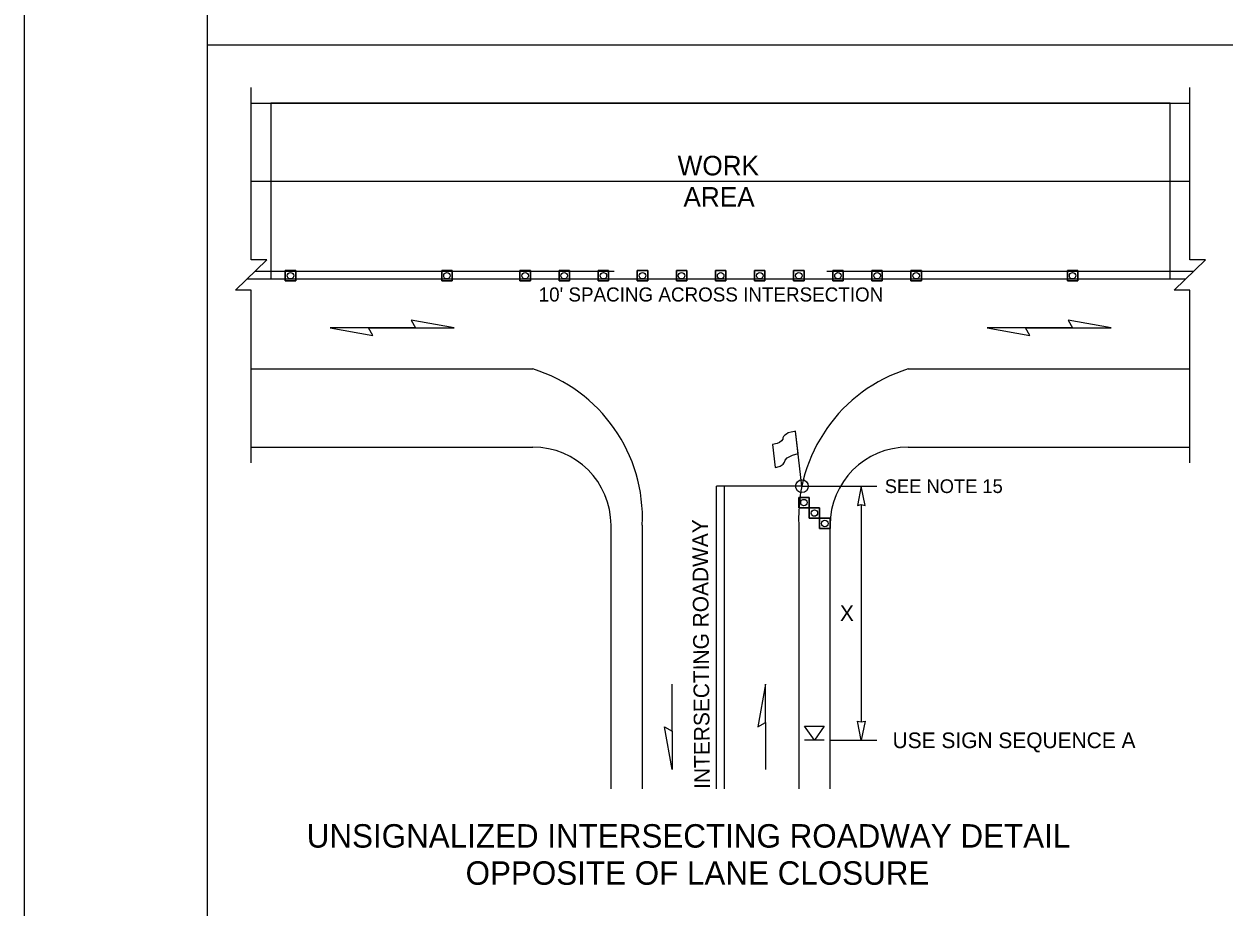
# Model space of a CAD drawing. Extents: x 99999.1 to 100095.7, y 99995 to 100010.7.
# Drawn here: x 100059.06 to 100065.2, y 100001.57 to 100006.09 of the extents above; entities that cross this region are included whole.
import ezdxf

# ---------------------------------------------------------------- set-up
doc = ezdxf.new("R2010")
doc.units = 0
for name, color, linetype in [('RD_ED_ShoulderPavedEdge', 7, 'Continuous'), ('RD_MK_LineDblYellowCenter', 7, 'Continuous'), ('RD_MK_LineEdgeWhite', 7, 'Continuous'), ('RD_MK_LineStop', 7, 'Continuous'), ('SH_DE_DetailBody1Text', 7, 'Continuous'), ('SH_DE_DetailHeading2Text', 7, 'Continuous'), ('SH_GI_PlotLimits', 7, 'Continuous'), ('SH_GI_SheetBorder', 7, 'Continuous'), ('TR_WZ_FlaggingStation', 7, 'Continuous'), ('TR_WZ_PortableSignMountBlk-Org', 7, 'Continuous'), ('TR_WZ_TrafficCone', 7, 'Continuous'), ('TR_WZ_WorkAreaLabel', 7, 'Continuous'), ('TR_WZ_WorkZoneDetails', 7, 'Continuous'), ('TR_WZ_WorkZoneTextCurrent', 7, 'Continuous')]:
    doc.layers.add(name, color=color, linetype=linetype)

msp = doc.modelspace()

# ---------------------------------------------------------------- linework, layer by layer
at = {"layer": 'RD_ED_ShoulderPavedEdge'}
for p, q in [((100060.225, 100005.6849), (100065.025, 100005.6849)), ((100060.225, 100003.9249), (100061.665, 100003.9249)), ((100063.585, 100003.9249), (100065.025, 100003.9249))]:
    msp.add_line(p, q, dxfattribs=at)
for points in [[(100062.065, 100002.1759), (100062.065, 100003.5249)], [(100063.185, 100002.1759), (100063.185, 100003.5249)]]:
    msp.add_lwpolyline(points, dxfattribs=at)
for centre, start, end in [((100061.665, 100003.5249), 0, 90), ((100063.585, 100003.5249), 90, 180)]:
    msp.add_arc(centre, 0.4, start, end, dxfattribs=at)
at = {"layer": 'RD_MK_LineDblYellowCenter'}
for p, q in [((100060.2457, 100004.8249), (100062.0812, 100004.8249)), ((100063.1688, 100004.8249), (100065.0457, 100004.8249)), ((100060.2043, 100004.7849), (100062.0812, 100004.7849)), ((100063.1688, 100004.7849), (100065.0043, 100004.7849)), ((100062.605, 100002.1759), (100062.605, 100003.7249)), ((100062.645, 100002.1759), (100062.645, 100003.7249))]:
    msp.add_line(p, q, dxfattribs=at)
at = {"layer": 'RD_MK_LineEdgeWhite'}
for p, q in [((100060.225, 100005.2849), (100065.025, 100005.2849)), ((100060.225, 100004.3249), (100061.665, 100004.3249)), ((100063.585, 100004.3249), (100065.025, 100004.3249)), ((100062.225, 100003.5249), (100062.225, 100002.1759)), ((100063.025, 100003.5249), (100063.025, 100002.1759))]:
    msp.add_line(p, q, dxfattribs=at)
for centre, start, end in [((100061.4258, 100003.5615), 357.37881, 72.60523), ((100063.8242, 100003.5615), 107.39477, 182.62119)]:
    msp.add_arc(centre, 0.8, start, end, dxfattribs=at)
at = {"layer": 'RD_MK_LineStop'}
msp.add_line((100063.041, 100003.7249), (100062.605, 100003.7249), dxfattribs=at)
at = {"layer": 'SH_GI_PlotLimits'}
msp.add_lwpolyline([(100059.0625, 99999.6875), (100076.0625, 99999.6875), (100076.0625, 100010.6875), (100059.0625, 100010.6875)], close=True, dxfattribs=at)
at = {"layer": 'SH_GI_SheetBorder'}
msp.add_line((100060, 100010.375), (100060, 100000), dxfattribs=at)
at = {"layer": 'TR_WZ_FlaggingStation'}
for p, q in [((100063.022, 100003.8918), (100063.0089, 100004.0062)), ((100063.041, 100003.7249), (100063.009, 100004.0059)), ((100062.891, 100003.9384), (100062.9043, 100003.8212)), ((100063.022, 100003.8918), (100063.022, 100003.8918))]:
    msp.add_line(p, q, dxfattribs=at)
for points in [[(100063.0089, 100004.0062), (100063.0032, 100004.0049), (100062.9854, 100004.0015), (100062.9715, 100003.9973), (100062.9619, 100003.9912), (100062.9533, 100003.9865), (100062.9477, 100003.9797), (100062.9434, 100003.9718), (100062.9429, 100003.9656), (100062.9375, 100003.9564), (100062.9267, 100003.949), (100062.9143, 100003.9438), (100062.891, 100003.9384)], [(100062.9043, 100003.8212), (100062.9124, 100003.8226), (100062.9301, 100003.8272), (100062.9458, 100003.8377), (100062.9523, 100003.8483), (100062.9562, 100003.8586), (100062.9653, 100003.8695), (100062.9763, 100003.8757), (100062.9936, 100003.8828), (100063.022, 100003.8918)]]:
    msp.add_lwpolyline(points, dxfattribs=at)
msp.add_circle((100063.041, 100003.7249), 0.0325, dxfattribs=at)
at = {"layer": 'TR_WZ_PortableSignMountBlk-Org'}
msp.add_line((100063.1549, 100002.4249), (100063.0549, 100002.4249), dxfattribs=at)
msp.add_lwpolyline([(100063.105, 100002.4249), (100063.0549, 100002.4968), (100063.1549, 100002.4968)], close=True, dxfattribs=at)
at = {"layer": 'TR_WZ_TrafficCone'}
for points in [[(100060.399, 100004.8283), (100060.4524, 100004.8283), (100060.4524, 100004.7749), (100060.399, 100004.7749), (100060.399, 100004.8283)], [(100060.399, 100004.7749), (100060.4524, 100004.7749), (100060.4524, 100004.8283), (100060.399, 100004.8283), (100060.399, 100004.7749)], [(100061.199, 100004.8283), (100061.2524, 100004.8283), (100061.2524, 100004.7749), (100061.199, 100004.7749), (100061.199, 100004.8283)], [(100061.199, 100004.7749), (100061.2524, 100004.7749), (100061.2524, 100004.8283), (100061.199, 100004.8283), (100061.199, 100004.7749)], [(100061.599, 100004.8283), (100061.6524, 100004.8283), (100061.6524, 100004.7749), (100061.599, 100004.7749), (100061.599, 100004.8283)], [(100061.599, 100004.7749), (100061.6524, 100004.7749), (100061.6524, 100004.8283), (100061.599, 100004.8283), (100061.599, 100004.7749)], [(100061.799, 100004.8283), (100061.8524, 100004.8283), (100061.8524, 100004.7749), (100061.799, 100004.7749), (100061.799, 100004.8283)], [(100061.799, 100004.7749), (100061.8524, 100004.7749), (100061.8524, 100004.8283), (100061.799, 100004.8283), (100061.799, 100004.7749)], [(100061.999, 100004.8283), (100062.0524, 100004.8283), (100062.0524, 100004.7749), (100061.999, 100004.7749), (100061.999, 100004.8283)], [(100061.999, 100004.7749), (100062.0524, 100004.7749), (100062.0524, 100004.8283), (100061.999, 100004.8283), (100061.999, 100004.7749)], [(100062.199, 100004.8283), (100062.2524, 100004.8283), (100062.2524, 100004.7749), (100062.199, 100004.7749), (100062.199, 100004.8283)], [(100062.199, 100004.7749), (100062.2524, 100004.7749), (100062.2524, 100004.8283), (100062.199, 100004.8283), (100062.199, 100004.7749)], [(100062.399, 100004.8283), (100062.4524, 100004.8283), (100062.4524, 100004.7749), (100062.399, 100004.7749), (100062.399, 100004.8283)], [(100062.399, 100004.7749), (100062.4524, 100004.7749), (100062.4524, 100004.8283), (100062.399, 100004.8283), (100062.399, 100004.7749)], [(100062.599, 100004.8283), (100062.6524, 100004.8283), (100062.6524, 100004.7749), (100062.599, 100004.7749), (100062.599, 100004.8283)], [(100062.599, 100004.7749), (100062.6524, 100004.7749), (100062.6524, 100004.8283), (100062.599, 100004.8283), (100062.599, 100004.7749)], [(100062.799, 100004.8283), (100062.8524, 100004.8283), (100062.8524, 100004.7749), (100062.799, 100004.7749), (100062.799, 100004.8283)], [(100062.799, 100004.7749), (100062.8524, 100004.7749), (100062.8524, 100004.8283), (100062.799, 100004.8283), (100062.799, 100004.7749)], [(100062.999, 100004.8283), (100063.0524, 100004.8283), (100063.0524, 100004.7749), (100062.999, 100004.7749), (100062.999, 100004.8283)], [(100062.999, 100004.7749), (100063.0524, 100004.7749), (100063.0524, 100004.8283), (100062.999, 100004.8283), (100062.999, 100004.7749)], [(100063.199, 100004.8283), (100063.2524, 100004.8283), (100063.2524, 100004.7749), (100063.199, 100004.7749), (100063.199, 100004.8283)], [(100063.199, 100004.7749), (100063.2524, 100004.7749), (100063.2524, 100004.8283), (100063.199, 100004.8283), (100063.199, 100004.7749)], [(100063.399, 100004.8283), (100063.4524, 100004.8283), (100063.4524, 100004.7749), (100063.399, 100004.7749), (100063.399, 100004.8283)], [(100063.399, 100004.7749), (100063.4524, 100004.7749), (100063.4524, 100004.8283), (100063.399, 100004.8283), (100063.399, 100004.7749)], [(100063.599, 100004.8283), (100063.6524, 100004.8283), (100063.6524, 100004.7749), (100063.599, 100004.7749), (100063.599, 100004.8283)], [(100063.599, 100004.7749), (100063.6524, 100004.7749), (100063.6524, 100004.8283), (100063.599, 100004.8283), (100063.599, 100004.7749)], [(100064.399, 100004.8283), (100064.4524, 100004.8283), (100064.4524, 100004.7749), (100064.399, 100004.7749), (100064.399, 100004.8283)], [(100064.399, 100004.7749), (100064.4524, 100004.7749), (100064.4524, 100004.8283), (100064.399, 100004.8283), (100064.399, 100004.7749)], [(100063.025, 100003.6142), (100063.025, 100003.6676), (100063.0783, 100003.6676), (100063.0783, 100003.6142), (100063.025, 100003.6142)], [(100063.0783, 100003.6142), (100063.0783, 100003.6676), (100063.025, 100003.6676), (100063.025, 100003.6142), (100063.0783, 100003.6142)], [(100063.0783, 100003.5609), (100063.0783, 100003.6142), (100063.1317, 100003.6142), (100063.1317, 100003.5609), (100063.0783, 100003.5609)], [(100063.1317, 100003.5609), (100063.1317, 100003.6142), (100063.0783, 100003.6142), (100063.0783, 100003.5609), (100063.1317, 100003.5609)], [(100063.1317, 100003.5076), (100063.1317, 100003.5609), (100063.185, 100003.5609), (100063.185, 100003.5076), (100063.1317, 100003.5076)], [(100063.185, 100003.5076), (100063.185, 100003.5609), (100063.1317, 100003.5609), (100063.1317, 100003.5076), (100063.185, 100003.5076)]]:
    msp.add_lwpolyline(points, dxfattribs=at)
for centre in [(100060.4257, 100004.8016), (100061.2257, 100004.8016), (100061.6257, 100004.8016), (100061.8257, 100004.8016), (100062.0257, 100004.8016), (100062.2257, 100004.8016), (100062.4257, 100004.8016), (100062.6257, 100004.8016), (100062.8257, 100004.8016), (100063.0257, 100004.8016), (100063.2257, 100004.8016), (100063.4257, 100004.8016), (100063.6257, 100004.8016), (100064.4257, 100004.8016), (100063.0517, 100003.6409), (100063.105, 100003.5876), (100063.1583, 100003.5342)]:
    msp.add_circle(centre, 0.0167, dxfattribs=at)
at = {"layer": 'TR_WZ_WorkZoneDetails'}
for p, q in [((100065.25, 100005.9805), (100060, 100005.9805)), ((100060.8244, 100004.5349), (100061.0656, 100004.5349)), ((100061.0656, 100004.5349), (100060.8244, 100004.5349)), ((100064.1844, 100004.5349), (100064.4256, 100004.5349)), ((100064.4256, 100004.5349), (100064.1844, 100004.5349)), ((100063.041, 100003.7249), (100063.425, 100003.7249)), ((100063.345, 100003.6312), (100063.345, 100002.5187)), ((100062.3772, 100002.4718), (100062.3772, 100002.7129)), ((100062.8545, 100002.5164), (100062.8545, 100002.2753)), ((100063.185, 100002.4249), (100063.425, 100002.4249))]:
    msp.add_line(p, q, dxfattribs=at)
for points in [[(100060.225, 100003.8449), (100060.225, 100004.7275), (100060.145, 100004.7275), (100060.305, 100004.8824), (100060.225, 100004.8824), (100060.225, 100005.7649)], [(100065.025, 100003.8449), (100065.025, 100004.7275), (100064.945, 100004.7275), (100065.105, 100004.8824), (100065.025, 100004.8824), (100065.025, 100005.7649)]]:
    msp.add_lwpolyline(points, dxfattribs=at)
for points in [[(100060.325, 100005.6849), (100060.325, 100004.7849), (100064.925, 100004.7849), (100064.925, 100005.6849)], [(100061.2621, 100004.5349), (100061.0433, 100004.5735), (100061.0656, 100004.5349)], [(100064.6221, 100004.5349), (100064.4033, 100004.5735), (100064.4256, 100004.5349)], [(100060.6279, 100004.5349), (100060.8467, 100004.4964), (100060.8244, 100004.5349)], [(100063.9879, 100004.5349), (100064.2067, 100004.4964), (100064.1844, 100004.5349)], [(100063.345, 100003.7249), (100063.3257, 100003.6266), (100063.345, 100003.6312), (100063.3643, 100003.6266)], [(100062.8545, 100002.7129), (100062.816, 100002.4941), (100062.8545, 100002.5164)], [(100063.345, 100002.4249), (100063.3257, 100002.5232), (100063.345, 100002.5187), (100063.3643, 100002.5232)], [(100062.3772, 100002.2753), (100062.3387, 100002.4941), (100062.3772, 100002.4718)]]:
    msp.add_lwpolyline(points, close=True, dxfattribs=at)

# ---------------------------------------------------------------- texts
at = {"layer": 'SH_DE_DetailBody1Text'}
msp.add_text('INTERSECTING ROADWAY', height=0.08, rotation=90.4626, dxfattribs=at).set_placement((100062.5709, 100002.1769))
at = {"layer": 'SH_DE_DetailHeading2Text'}
for s, p in [('UNSIGNALIZED INTERSECTING ROADWAY DETAIL', (100060.5086, 100001.8759)), ('OPPOSITE OF LANE CLOSURE', (100061.3211, 100001.6859))]:
    msp.add_text(s, height=0.12, rotation=360, dxfattribs=at).set_placement(p)
at = {"layer": 'TR_WZ_WorkAreaLabel'}
for s, p in [('WORK', (100062.4058, 100005.3149)), ('AREA', (100062.4354, 100005.1549))]:
    msp.add_text(s, height=0.1, dxfattribs=at).set_placement(p)
at = {"layer": 'TR_WZ_WorkZoneTextCurrent'}
for s, height, p in [("10' SPACING ACROSS INTERSECTION", 0.072, (100061.6948, 100004.6696)), ('SEE NOTE 15', 0.07, (100063.465, 100003.6899)), ('X', 0.08, (100063.2356, 100003.0349)), ('USE SIGN SEQUENCE A', 0.08, (100063.505, 100002.3849))]:
    msp.add_text(s, height=height, dxfattribs=at).set_placement(p)

doc.saveas('drawing.dxf')
